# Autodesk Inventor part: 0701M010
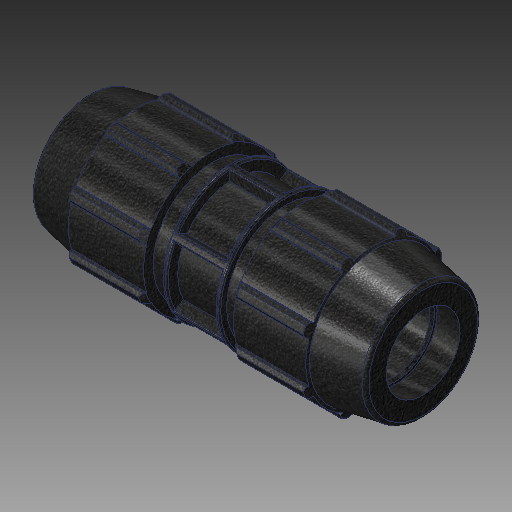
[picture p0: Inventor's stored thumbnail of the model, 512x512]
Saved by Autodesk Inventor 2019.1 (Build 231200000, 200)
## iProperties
Created: 2017-02
Part Number: 0701M010
Material: PVC-Piping
Description: PLASSON COUPLER 1'' - 32mm
Document SubType Name: Modeling
Designer: KIM
Mass: 92.6774 g
Surface Area: 199.44 cm^2
Volume: 66.1981 cm^3
Density: 1.4 g/cm^3
Appearance: PTFE
Author: KIM
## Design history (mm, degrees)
derived "0701M.ipt"
feature "Solid1::0701M.ipt"
tag "TaggingFeature1"
body "Solid1"
other parameters: "d2" = 32, "d4" = 12.08617, "d5" = 20.71914, "d7" = 64.008, "d8" = 48.006, "d9" = 20.71914, "d11" = 2.07191, "d12" = 51.2064, "d13" = 120 deg, "d14" = 49.95, "d15" = 10 deg, "d16" = 57.6072, "d18" = 1.665, "d19" = 35 deg, "d20" = 17.5 deg, "d21" = 59.52744, "d23" = 0, "d25" = 360 deg, "d27" = 1.28016, "d33" = 0.666, "d34" = 3.2004, "d36" = 0, "d37" = 0.666, "d38" = 0.666, "d40" = 360 deg, "d42" = 31.90748, "d43" = 1.92024, "d46" = 0.999, "d50" = 26.64, "d51" = 70.104, "d53" = 2.07191, "d54" = 31.90748, "d55" = 120 deg, "d56" = 12 deg, "d57" = 12.08617, "d58" = 145.034, "d59" = 20.71914, "d63" = 20.71914, "d68" = 0, "d69" = 0.666, "d70" = 1.665, "d72" = 0, "d73" = 1.92024, "d77" = 70.104, "d78" = 33.3, "d_" = 33.3, "E_" = 64.008, "H_" = 145.034, "l_" = 70.104, "d_1" = 32
